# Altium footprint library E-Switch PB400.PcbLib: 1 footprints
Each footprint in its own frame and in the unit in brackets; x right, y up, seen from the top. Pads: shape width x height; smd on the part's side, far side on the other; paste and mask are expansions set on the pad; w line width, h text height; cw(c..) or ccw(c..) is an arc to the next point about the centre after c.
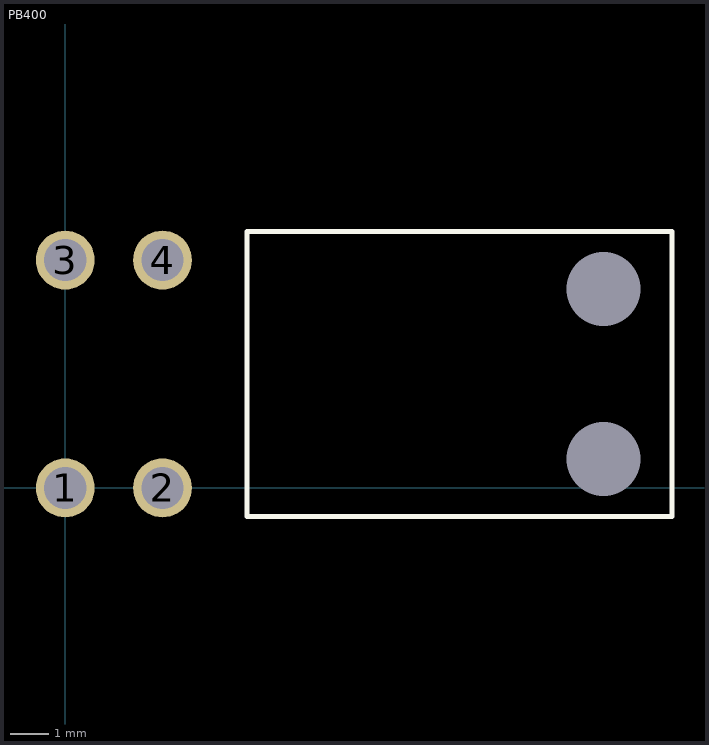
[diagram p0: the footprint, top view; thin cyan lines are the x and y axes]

## PB400 [mil]
pads (6):
  round 60 hole 43: 1(0,0) 2(99,0) 3(0,232) 4(99,232)
  round 0 hole 75: ""(548,29.5) ""(548,202.5)
Top Overlay:
  lines w5: 185,-29 185,261 618,261 618,-29 185,-29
